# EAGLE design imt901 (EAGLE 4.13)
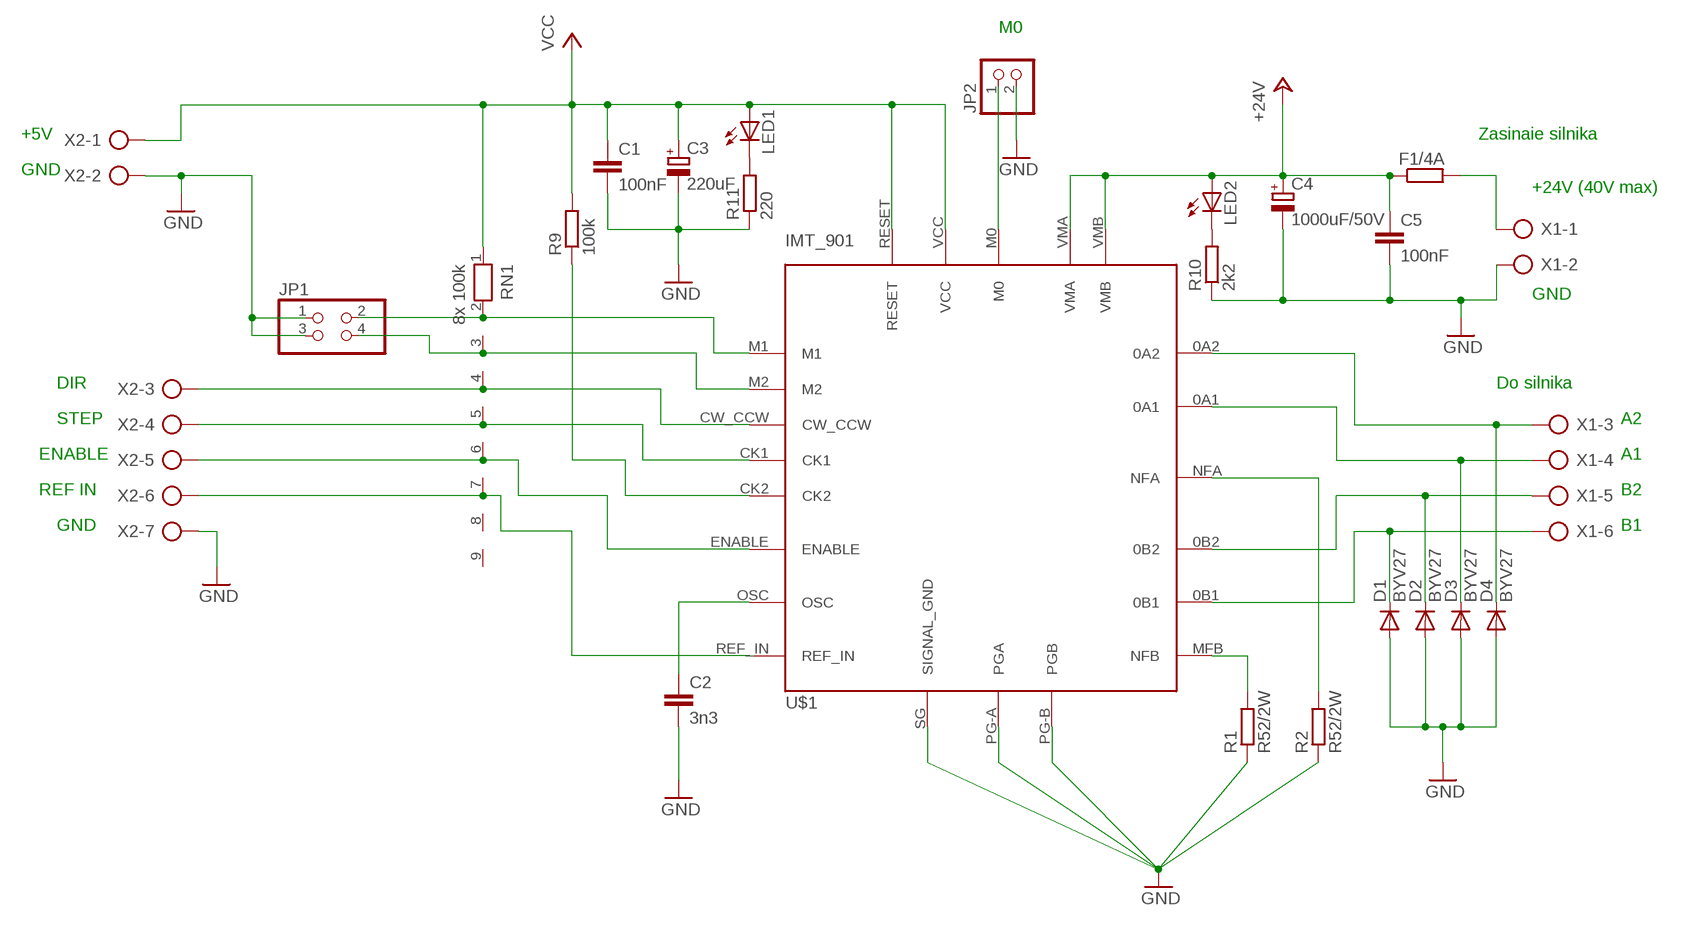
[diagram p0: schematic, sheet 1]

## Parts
C1  100nF  C-EU025-050X050  [C025-050X050]
C2  3n3  C-EU025-050X050  [C025-050X050]
C3  220uF  CPOL-EUE2.5-5  [E2,5-5]
C4  1000uF/50V  CPOL-EUE3.5-8  [E3,5-8]
C5  100nF  C-EU025-050X050  [C025-050X050]
D1  BYV27  [SOD57-10]
D2  BYV27  [SOD57-10]
D3  BYV27  [SOD57-10]
D4  BYV27  [SOD57-10]
F1/4A  R-EU_0207/10  [0207/10]
JP1  PINHD-2X2  [2X02]
JP2  PINHD-1X2  [1X02]
LED1  LED3MM  [LED3MM]
LED2  LED3MM  [LED3MM]
R1  R52/2W  R-EU_0309/12  [0309/12]
R2  R52/2W  R-EU_0309/12  [0309/12]
R9  100k  R-EU_0204/7  [0204/7]
R10  2k2  R-EU_0204/7  [0204/7]
R11  220  R-EU_0204/7  [0204/7]
RN1  8x 100k  RN08  [RN-9]
U$1  IMT_901  [CPP-25]
X1  AK500/6  [AK500/6]
X2  AK500/7  [AK500/7]

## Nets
+24V: C4.+ C5.1 F1/4A.1 LED2.A U$1.VMA U$1.VMB
GND: C1.2 C2.2 C3.- C4.- C5.2 D1.A D2.A D3.A D4.A JP1.1 JP1.3 JP2.2 R1.1 R2.1 R10.1 R11.1 U$1.PG-A(PGA) U$1.PG-B(PGB) U$1.SG(SIGNAL_GND) X1.2 X2.2 X2.7
N$1: JP1.2 RN1.2 U$1.M1
N$2: JP1.4 RN1.3 U$1.M2
N$3: RN1.4 U$1.CW_CCW X2.3
N$4: RN1.5 U$1.CK1 X2.4
N$5: R9.1 U$1.CK2
N$6: RN1.6 U$1.ENABLE X2.5
N$7: RN1.7 U$1.REF_IN X2.6
N$8: JP2.1 U$1.M0
N$9: F1/4A.2 X1.1
N$10: D2.C U$1.0B2 X1.5
N$11: LED2.K(C) R10.2
N$12: LED1.K(C) R11.2
N$14: R1.2 U$1.MFB(NFB)
N$15: R2.2 U$1.NFA
N$17: C2.1 U$1.OSC
N$19: D3.C U$1.0A1 X1.4
N$20: D4.C U$1.0A2 X1.3
N$21: D1.C U$1.0B1 X1.6
VCC: C1.1 C3.+ LED1.A R9.2 RN1.1 U$1.RESET U$1.VCC X2.1
Unconnected: RN1.8 RN1.9

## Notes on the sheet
- M0
- +5V | Zasinaie silnika
- GND
- +24V (40V max)
- GND
- DIR | Do silnika
- STEP | A2
- ENABLE | A1
- REF IN | B2
- GND | B1

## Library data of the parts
C1 C2 C5 = rcl:C-EU: CAPACITOR, European symbol
C3 C4 = rcl:CPOL-EU: POLARIZED CAPACITOR, European symbol
D1-D4 = diode:BYV27: DIODE
F1/4A R1 R2 R9-R11 = rcl:R-EU_: RESISTOR, European symbol
JP1 = pinhead:PINHD-2X2: PIN HEADER
JP2 = pinhead:PINHD-1X2: PIN HEADER
LED1 LED2 = led:LED: LED
RN1 = resistor-net:RN08: RESISTOR NETWORK
U$1 = stepper:IMT_901
X1 = con-ptr500:AK500/6: CONNECTOR
X2 = con-ptr500:AK500/7: CONNECTOR

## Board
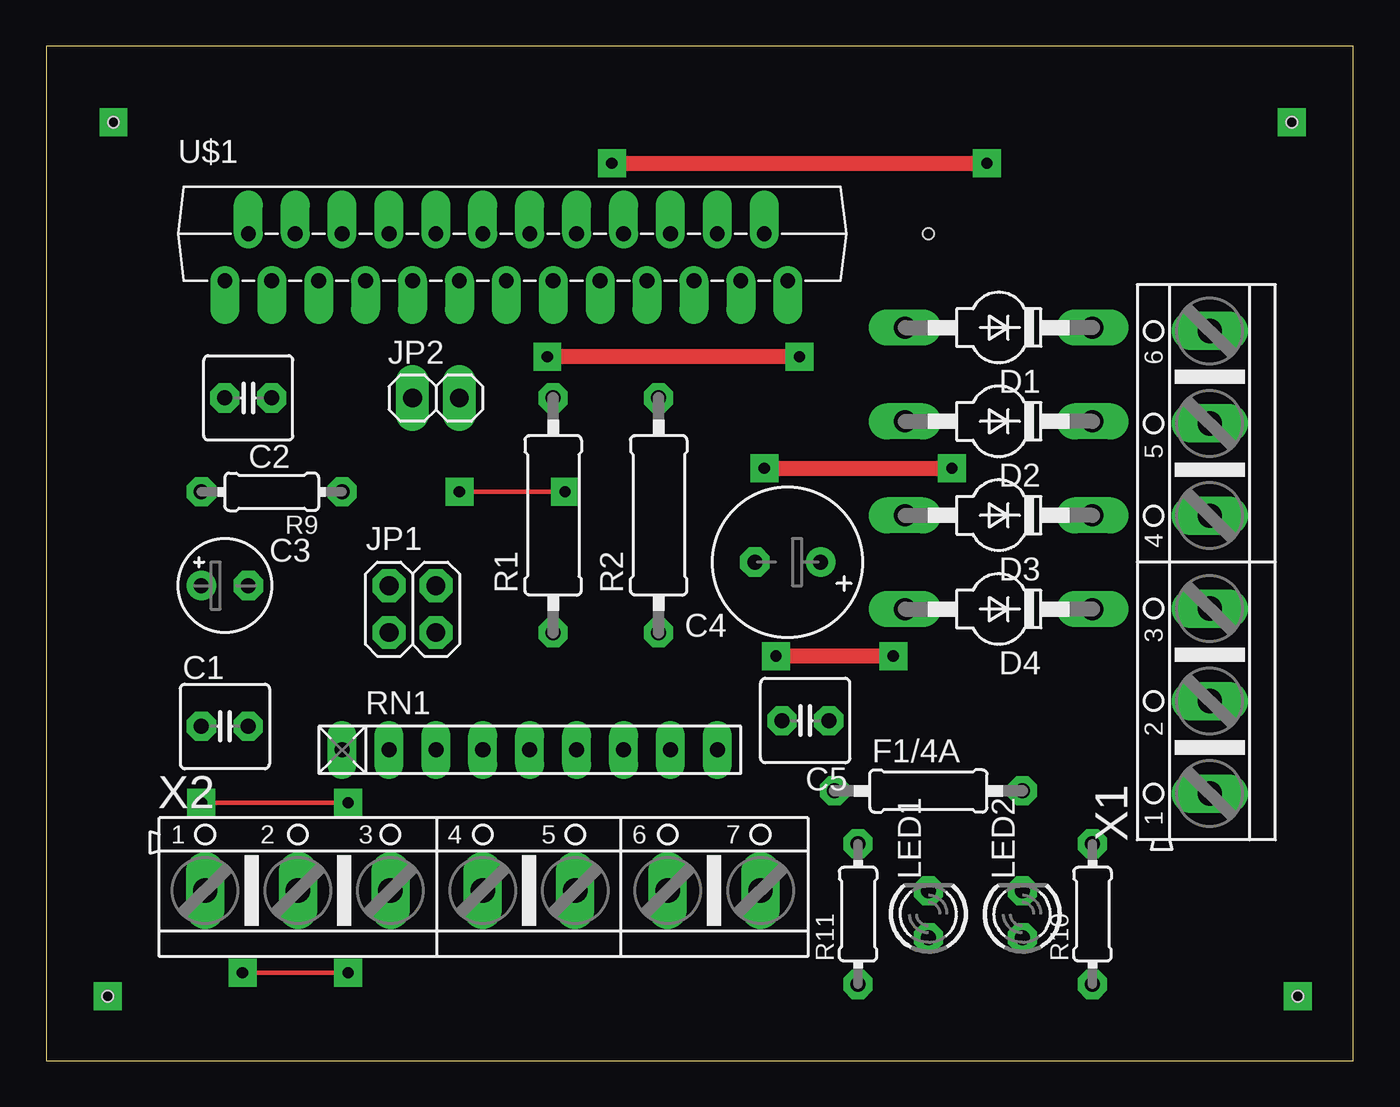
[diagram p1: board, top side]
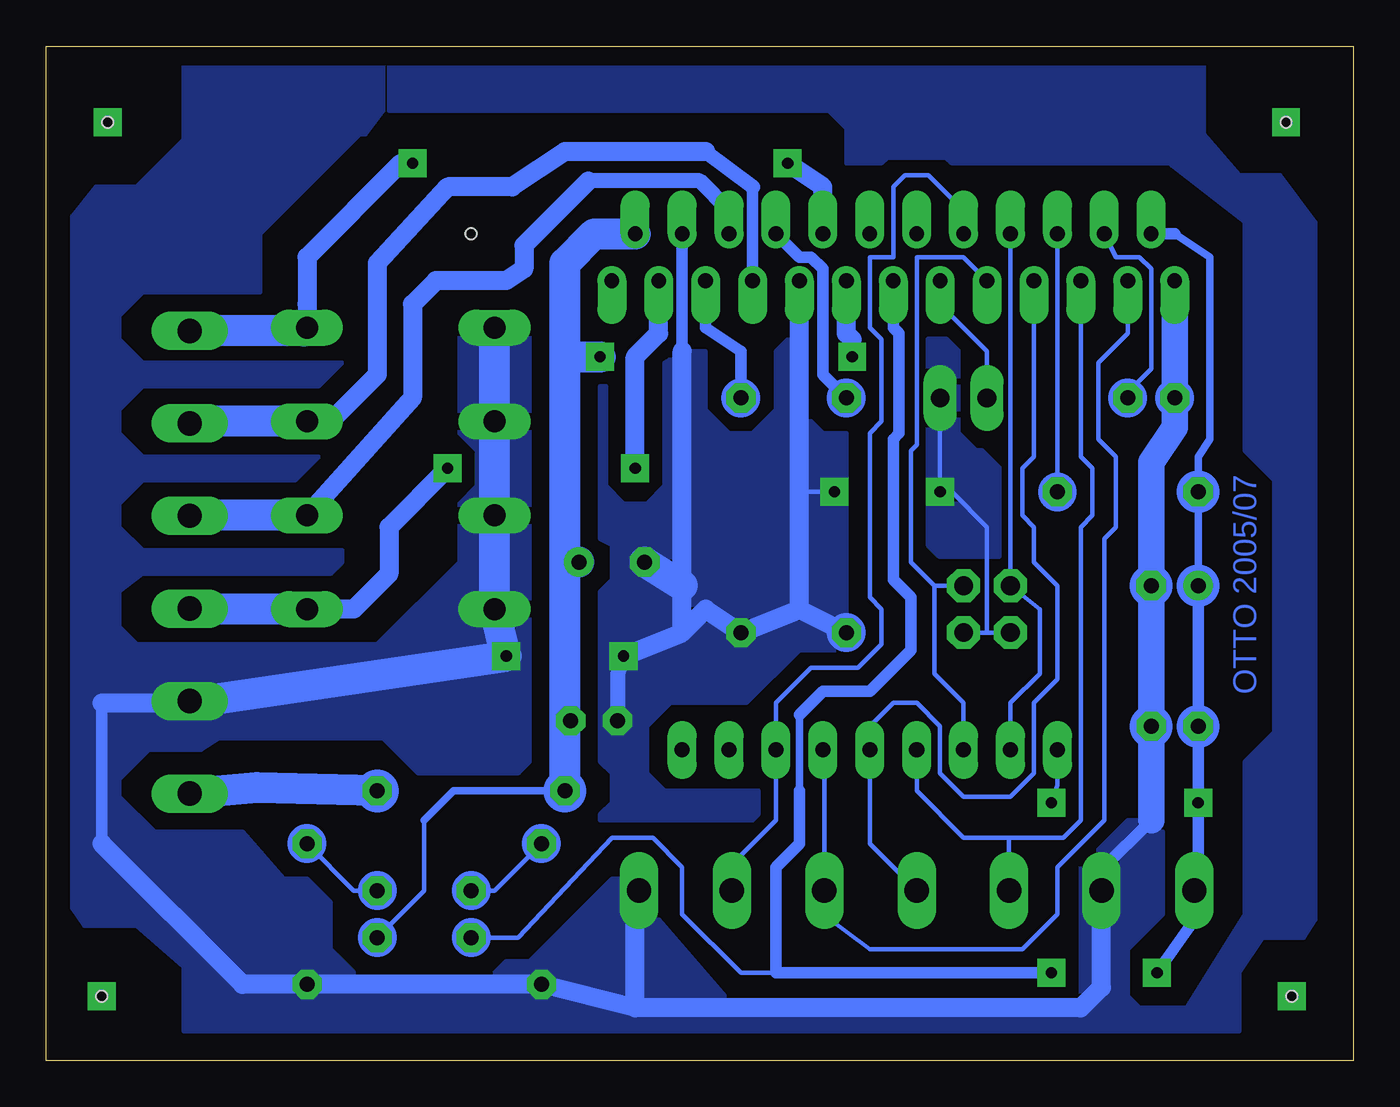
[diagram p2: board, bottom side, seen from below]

Size 70.79 x 54.92 mm. Coordinates in mm from the lower left corner, seen from the top.
Outline: 0,0 70.79,0 70.79,54.92 0,54.92 0,0
Copper layers (1*16): Top 0.035mm / dielectric 1.5mm / Bottom 0.035mm
Design rules "default": minimum track width 10mil, minimum drill 24mil, track to track 0mil, track to pad 8mil, pad to pad 8mil, via to via 8mil, smd to smd 8mil, copper to edge 40mil, drill to drill 8mil, minimum pad ring 15mil, minimum via ring 18mil, stop-mask expansion 4mil, vias tented up to drill 0mil, thermal gap 10mil
Holes 0.6 mm at 3.65,50.8 3.33,3.49 47.78,44.76 67.46,50.8 67.78,3.49

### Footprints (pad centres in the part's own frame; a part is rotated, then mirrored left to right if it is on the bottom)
C025-050X050 = drill 0.813 octagon: 1 -1.27,0; 2 1.27,0
E2,5-5 = drill 0.813 pad 1.6 round: + -1.27,0 | drill 0.813 pad 1.6 octagon: - 1.27,0
E3,5-8 = drill 0.813 pad 1.6 round: + -1.778,0 | drill 0.813 pad 1.6 octagon: - 1.778,0
SOD57-10 = drill 1.194 long: A 5.08,0; C -5.08,0
0207/10 = drill 0.813 octagon: 1 -5.08,0; 2 5.08,0
2X02 = drill 1.016 octagon: 1 -1.27,-1.27; 2 -1.27,1.27; 3 1.27,-1.27; 4 1.27,1.27
1X02 = drill 1.016 long: 1 -1.27,0; 2 1.27,0
LED3MM = drill 0.813 octagon: A -1.27,0; K 1.27,0
0309/12 = drill 0.813 octagon: 1 -6.35,0; 2 6.35,0
0204/7 = drill 0.813 octagon: 1 -3.81,0; 2 3.81,0
RN-9 = drill 0.813 long: 1 -10.16,0; 2 -7.62,0; 3 -5.08,0; 4 -2.54,0; 5 0,0; 6 2.54,0; 7 5.08,0; 8 7.62,0; 9 10.16,0
CPP-25 = drill 0.8 offset: 0A1 26.67,2.54; 0A2 30.48,0; 0B1 21.59,2.54; 0B2 25.4,0; CK1 10.16,0; CK2 8.89,2.54; CW_CCW 7.62,0; ENABLE 5.08,0; M0 15.24,0; M1 11.43,2.54; M2 12.7,0; MFB 24.13,2.54; NC 16.51,2.54; NC1 19.05,2.54; NC2 33.02,0; NFA 27.94,0; OSC 6.35,2.54; PG-A 29.21,2.54; PG-B 22.86,0; REF_IN 13.97,2.54; RESET 3.81,2.54; SG 2.54,0; VCC 17.78,0; VMA 31.75,2.54; VMB 20.32,0
AK500/6 = drill 1.321 long: 1 -12.522,0; 2 -7.518,0; 3 -2.515,0; 4 2.515,0; 5 7.518,0; 6 12.522,0
AK500/7 = drill 1.321 long: 1 -15.037,0; 2 -10.008,0; 3 -5.004,0; 4 0,0; 5 5.004,0; 6 10.008,0; 7 15.037,0

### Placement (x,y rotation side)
C1  9.68,18.09 0 top
C2  10.95,35.87 180 top
C3  9.68,25.71 0 top
C4  40.16,26.98 180 top
C5  41.11,18.41 180 top
D1  51.59,39.68 180 top
D2  51.59,34.6 180 top
D3  51.59,29.52 180 top
D4  51.59,24.44 180 top
F1/4A  47.78,14.6 0 top
JP1  19.84,24.44 0 top
JP2  21.11,35.87 0 top
LED1  47.78,7.93 90 top
LED2  52.86,7.93 90 top
R1  27.46,29.52 90 top
R2  33.17,29.52 90 top
R9  12.22,30.79 180 top
R10  56.67,7.93 90 top
R11  43.97,7.93 90 top
RN1  26.19,16.82 0 top
U$1  7.14,42.22 0 top
X1  63.02,26.98 90 top
X2  23.65,9.2 0 top

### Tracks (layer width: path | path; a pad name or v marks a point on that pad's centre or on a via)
+24V  (via drill 0.6)
  Top 0.813: v40.79,38.1 v27.14,38.1
  Bottom 0.254: 50.32,13.01 50.32,9.2 LED2.A
  Bottom 0.406: F1/4A.1 48.73,14.6 50.32,13.01
  Bottom 0.813: 42.7,18.41 C5.1
  Bottom 1.016: v27.14,38.1 27.14,39.05 27.46,39.36 U$1.VMB
  Bottom 1.676: U$1.VMA 41.11,44.76 42.7,43.18 42.7,38.1 | F1/4A.1 42.7,18.41 42.7,26.98 | 42.7,26.98 42.7,38.1 | 42.7,38.1 v40.79,38.1 | 42.7,26.98 C4.+
GND  (via drill 0.6)
  Top 0.254: v28.09,30.79 v22.38,30.79
  Top 0.813: v45.87,21.9 v39.52,21.9
  Bottom 0.254: 38.89,9.2 X2.7 | 64.29,19.36 X1.2 63.02,19.36 | X2.2 13.64,10.32 | JP2.2 v22.38,30.79 21.74,30.79 19.84,28.89 19.84,23.17 | 19.84,23.17 JP1.1 | 30,30.79 v28.09,30.79 | 19.84,23.17 JP1.3
  Bottom 0.61: 67.78,11.74 67.78,19.36 | 13.64,10.32 10.95,13.01 | 36.35,38.41 U$1.PG-A
  Bottom 0.813: C5.2 39.84,20.95 v39.52,21.9
  Bottom 1.016: 67.78,19.36 64.29,19.36 | X2.2 13.64,3.97 14.76,2.85 38.89,2.85 | 38.89,2.85 R11.1 R10.1 60.16,4.12 67.78,11.74 | 38.89,2.85 38.89,9.2 | v39.52,21.9 36.35,23.17 | 36.35,23.17 35.08,24.44 R2.1 30,24.44 | 36.35,23.17 36.35,25.71 36.35,38.41 | 30,24.44 30,30.79 U$1.PG-B | 30,24.44 R1.1
  Bottom 1.422: 10.95,13.01 C1.2 C3.- 10.95,32.38 9.68,34.29 C2.2 U$1.SG
  Bottom 1.676: D1.A D2.A D3.A D4.A v45.87,21.9 63.02,19.36 | 36.35,25.71 C4.-
N$1
  Bottom 0.254: U$1.M1 JP1.2 16.98,24.44 16.98,20.95 18.57,19.36 RN1.2
N$2
  Bottom 0.254: U$1.M2 21.11,43.49 23.65,43.49 23.65,33.33 23.96,33.02 23.96,26.98 22.69,25.71 | 22.69,25.71 JP1.4 | 22.69,25.71 22.69,20.95 21.11,19.36 RN1.3
N$3
  Bottom 0.254: U$1.CW_CCW 14.76,32.7 14.12,32.06 14.12,29.52 14.76,28.89 14.76,13.01 15.71,12.06 18.57,12.06 | 18.57,12.06 21.11,12.06 23.65,14.6 RN1.4 | X2.3 18.64,11.98 18.57,12.06
N$4
  Bottom 0.254: U$1.CK1 17.3,32.7 17.93,32.06 17.93,29.52 17.3,28.89 17.3,26.98 16.03,25.71 16.03,20.63 17.3,19.36 17.3,15.55 18.57,14.28 21.11,14.28 22.38,15.55 22.38,18.09 23.65,19.36 24.92,19.36 26.19,18.09 RN1.5 26.19,11.74 X2.4
N$5
  Bottom 0.254: R9.1 U$1.CK2
N$6
  Bottom 0.254: RN1.6 28.65,16.75 X2.5 28.73,9.2 28.73,7.93 26.19,6.03 17.93,6.03 16.03,7.93 16.03,10.47 13.49,13.01 13.49,28.25 12.85,28.89 12.85,32.7 13.8,33.65 13.8,37.78 12.22,39.36 U$1.ENABLE
N$7
  Bottom 0.254: U$1.REF_IN 21.11,46.03 23.01,47.94 24.28,47.94 24.92,47.3 24.92,43.49 26.19,43.49 26.19,39.68 25.55,39.05 25.55,34.6 26.19,33.97 26.19,25.08 25.55,24.44 25.55,22.54 26.82,21.27 29.36,21.27 31.27,19.36 RN1.7 31.27,13.01 33.81,10.47 X2.6
N$8
  Bottom 0.254: U$1.M0 22.38,40.95 19.84,38.41 JP2.1
N$9
  Bottom 1.676: X1.1 59.39,14.78 F1/4A.2
N$10
  Bottom 0.61: U$1.0B2 32.54,47.3
  Bottom 0.813: 32.54,47.3 35.08,49.21
  Bottom 1.016: 35.08,49.21 42.7,49.21 45.55,47.3 49.05,47.3 52.86,43.18 52.86,37.14 55.4,34.6 D2.C | 63.02,34.6 X1.5
  Bottom 1.676: D2.C 63.02,34.6
N$11
  Bottom 0.254: LED2.K 54.13,9.2 R10.2
N$12
  Bottom 0.254: LED1.K 46.51,9.2 R11.2
N$13
  pour Bottom: 27.46,33.97 28.73,33.97 30,35.24 30,39.68 31.27,38.41 31.27,35.24 32.54,33.97 33.81,33.97 35.08,35.24 35.08,38.41 36.35,38.41 37.3,37.78 37.3,31.11 38.25,30.16 39.52,30.16 40.48,31.11 40.48,36.51 40.79,36.51 40.79,28.25 40.16,27.93 40.16,26.03 40.79,25.39 40.79,16.19 40.16,15.55 40.16,13.96 40.79,13.33 40.79,13.01 32.54,13.01 32.22,13.33 32.22,14.6 37.3,14.6 38.25,15.55 38.25,18.09 36.98,19.36 32.85,19.36 30,22.22 27.46,22.22
N$14
  Bottom 0.61: U$1.MFB 30,43.49 29.36,43.49 28.73,42.86 28.73,37.14 R1.2
N$15
  Bottom 0.61: R2.2 33.17,38.41 35.08,39.68 U$1.NFA
N$16
  pour Bottom: 44.6,40 48.41,40 48.41,33.97 47.46,33.02 47.46,31.11 48.41,30.16 48.41,26.98 52.86,22.54 65.88,22.54 66.83,23.49 66.83,25.39 65.56,26.35 55.4,26.35 54.76,26.98 54.76,27.62 65.56,27.62 66.83,28.89 66.83,30.16 65.56,31.43 57.3,31.43 56.03,32.7 65.56,32.7 66.83,33.97 66.83,35.24 65.56,36.51 56.03,36.51 54.76,37.78 65.56,37.78 66.83,39.05 66.83,40.32 65.56,41.59 59.21,41.59 59.21,44.76 53.81,50.16 53.49,50.16 52.54,51.43 52.54,53.97 63.34,53.97 63.34,49.84 65.88,47.3 68.1,47.3 69.37,45.72 69.37,8.25 68.73,7.3 65.88,7.3 63.34,5.08 63.34,1.58 6.19,1.58 6.19,4.76 4.92,6.66 2.69,6.66 2.06,7.62 2.06,45.4 3.96,47.94 6.19,47.94 8.09,50.16 8.09,53.97 52.22,53.97 52.22,51.43 28.41,51.43 27.46,50.48 27.46,48.57 25.55,48.57 25.23,48.89 22.06,48.89 21.74,48.57 10,48.57 5.87,45.4 5.87,33.02 4.28,31.43 4.28,17.77 5.87,16.19 5.87,7.93 9.04,2.85 11.58,2.85 12.22,3.49 12.22,6.03 10.31,7.93 10.31,12.38 10.95,13.01 12.22,13.01 14.76,10.47 14.76,3.49 15.39,2.85 33.49,2.85 39.52,9.84 40.16,9.84 44.6,5.39 45.87,5.39 47.14,4.12 53.49,4.12 55.4,6.03 55.4,8.57 56.67,9.84 57.94,9.84 60.16,12.38 64.92,12.38 66.83,14.28 66.83,15.23 65.24,16.82 62.38,16.82 61.43,17.46 52.54,17.46 50.63,15.55 45.24,15.55 44.6,16.19
N$17
  Bottom 0.254: U$1.OSC 12.85,43.49 11.58,43.49 10.95,42.86 10.95,37.46 12.22,36.19 C2.1
N$18  (via drill 0.6)
  other vias: 3.65,50.8
N$19
  Bottom 0.813: 33.81,46.03 35.4,47.62 41.43,47.62
  Bottom 1.016: 41.43,47.62 44.92,44.13 44.92,42.86 45.87,42.22 49.68,42.22 50.95,40.95 50.95,35.87 D3.C | U$1.0A1 33.81,46.03
  Bottom 1.27: 63.02,29.52 X1.4
  Bottom 1.676: D3.C 63.02,29.52
N$20  (via drill 0.6)
  Top 0.813: v38.89,32.06 v49.05,32.06
  Bottom 0.254: 63.02,24.44 X1.3
  Bottom 1.016: v38.89,32.06 38.89,38.1 37.62,39.36 U$1.0A2 | v49.05,32.06 52.22,28.89 52.22,26.35 54.13,24.44 D4.C
  Bottom 1.676: D4.C 63.02,24.44
N$21  (via drill 0.6)
  Top 0.813: v30.63,48.57 v50.95,48.57
  Bottom 0.254: 56.67,40.95 56.85,39.5
  Bottom 1.016: v50.95,48.57 51.59,48.57 56.67,43.49 56.67,40.95 D1.C | v30.63,48.57 28.73,47.3 U$1.0B1
  Bottom 1.676: 56.85,39.5 X1.6
N$22  (via drill 0.6)
  other vias: 3.33,3.49
N$23  (via drill 0.6)
  other vias: 67.78,3.49
N$24  (via drill 0.6)
  other vias: 67.46,50.8
N$25
  pour Bottom: 19.2,27.3 22.38,27.3 23.01,27.93 23.01,39.05 22.06,39.05 21.43,38.41 21.43,33.97 20.47,33.02 20.16,33.02 19.2,32.06
VCC  (via drill 0.6)
  Top 0.254: v10.63,4.76 v16.35,4.76 | v8.41,13.97 v16.35,13.97
  Bottom 0.254: 8.41,10.47 X2.1 8.41,9.2 | LED1.A 45.24,6.66 40.16,12.06 37.94,12.06 36.35,10.47 36.35,7.93 33.17,4.76 31.27,4.76 | v16.35,13.97 16.03,14.92 RN1.1
  Bottom 0.406: C3.+ R9.2 8.41,32.7 7.77,33.65 7.77,43.49 9.68,44.76 | 30,14.6 30,18.73
  Bottom 0.61: 8.41,10.47 v8.41,13.97 C1.1 C3.+ | 9.68,44.76 U$1.RESET | 30,18.73 28.73,20 26.19,20 23.96,22.22 23.96,25.08 24.92,26.03 24.92,33.65 24.6,33.97 24.6,39.36 24.92,39.68 U$1.VCC | 30,14.6 30,11.74 31.27,10.47 31.27,4.76 v16.35,4.76 | v10.63,4.76 8.41,7.93 8.41,9.2
(copper drawn outside any net)
  shapes: Bottom circle x19

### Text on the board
Bottom: OTTO 2005/07
tValues: CNC STEP DRV | CNC-SD-2.0 | 2A-8S | B1 | B2 | A1 | 1 | A2 | 2 | - | R1,R2 | 40Vmax | Mot.Sup. | + | 0.8R-1A 0.52R-1.5A 0.4R-2A | JP1 MODE | 1 | S S 1/1 | O S 1/2 | 2 | S O 1/4 | PWR | O O 1/8 | +5V | GND | DIR | CK1 | EN. | REF | GND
